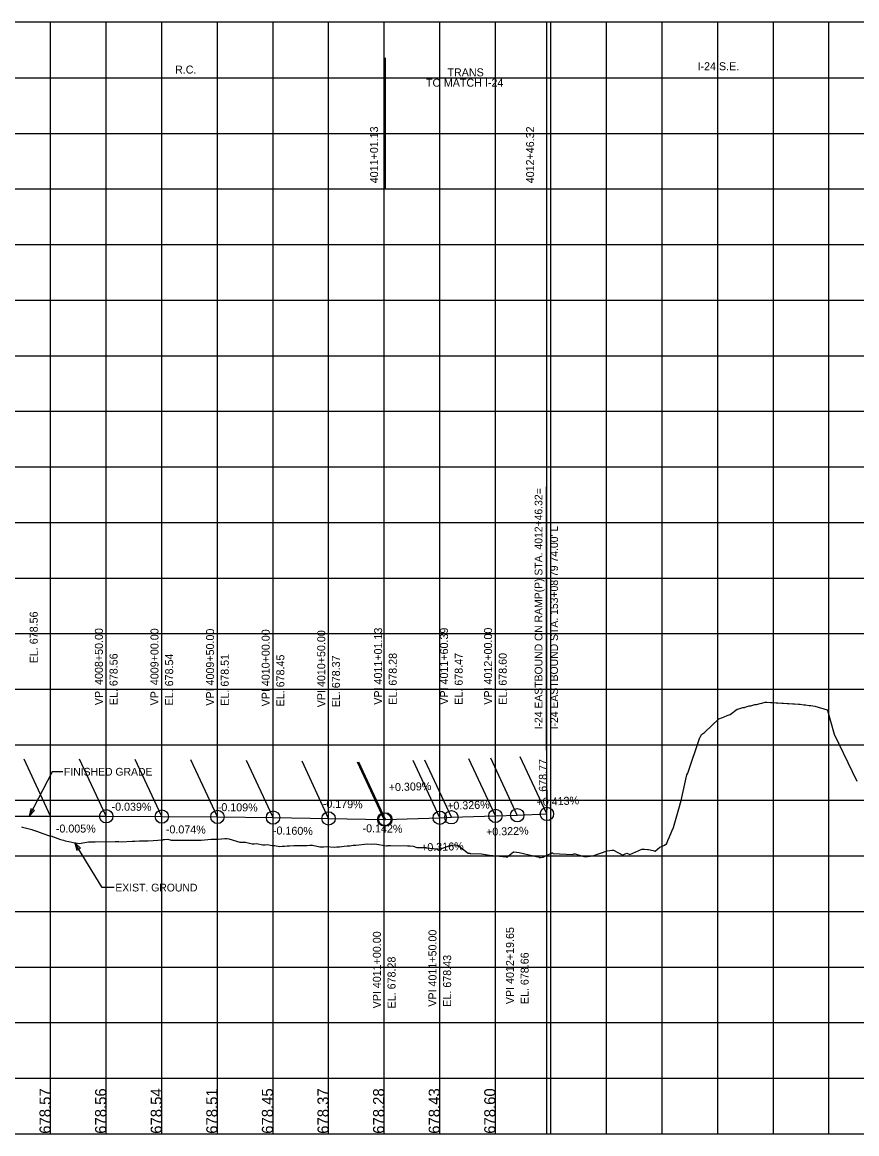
# Model space of a CAD drawing. Extents: x -7164 to 2214450, y -19642 to 253469.
# Drawn here: x 774 to 1525, y 6000 to 7000 of the extents above; entities that cross this region are included whole.
import ezdxf

# ---------------------------------------------------------------- set-up
doc = ezdxf.new("R2010")
doc.units = 0
for name, color, linetype in [('DESIGN - PROFILE - Proposed', 7, 'Continuous'), ('DESIGN - PROFILE - Proposed Curve Text', 7, 'Continuous'), ('DESIGN - PROFILE - Proposed Text', 7, 'Continuous'), ('DESIGN - SCRATCH - User 1', 7, 'Continuous'), ('DESIGN - SHEET - Light Grid', 7, 'Continuous'), ('SURVEY - PROFILE - Ground Line with Text', 7, 'Continuous')]:
    doc.layers.add(name, color=color, linetype=linetype)

msp = doc.modelspace()

# ---------------------------------------------------------------- linework, layer by layer
at = {"layer": 'DESIGN - PROFILE - Proposed'}
for p, q in [((766.8, 6285.6), (800, 6285.7)), ((766.8, 6285.6), (800, 6285.7)), ((800, 6285.7), (850, 6285.6)), ((800, 6285.7), (850, 6285.6)), ((850, 6285.6), (900, 6285.4)), ((850, 6285.6), (900, 6285.4)), ((900, 6285.4), (950, 6285.1)), ((900, 6285.4), (950, 6285.1)), ((950, 6285.1), (1000, 6284.5)), ((950, 6285.1), (1000, 6284.5)), ((1000, 6284.5), (1050, 6283.7)), ((1000, 6284.5), (1050, 6283.7)), ((1050, 6283.7), (1100, 6282.8)), ((1050, 6283.7), (1100, 6282.8)), ((1100, 6282.8), (1101.1, 6282.8)), ((1100, 6282.8), (1101.1, 6282.8)), ((1101.1, 6282.8), (1150, 6284.3)), ((1101.1, 6282.8), (1150, 6284.3)), ((1150, 6284.3), (1160.4, 6284.7)), ((1150, 6284.3), (1160.4, 6284.7)), ((1160.4, 6284.7), (1200, 6286)), ((1160.4, 6284.7), (1200, 6286)), ((1200, 6286), (1219.7, 6286.6)), ((1200, 6286), (1219.7, 6286.6)), ((1219.7, 6286.6), (1246.3, 6287.7)), ((1219.7, 6286.6), (1246.3, 6287.7))]:
    msp.add_line(p, q, dxfattribs=at)
at = {"layer": 'DESIGN - PROFILE - Proposed Curve Text'}
for p, q in [((1101.1, 6850), (1101.1, 6968.1)), ((1101.1, 6850), (1101.1, 6968.1)), ((1246.3, 6850), (1246.3, 6968.1)), ((1246.3, 6850), (1246.3, 6968.1)), ((741.8, 6950), (1101.1, 6950)), ((741.8, 6950), (1101.1, 6950)), ((1101.1, 6950), (1246.3, 6950)), ((1101.1, 6950), (1246.3, 6950)), ((1246.3, 6950), (2600, 6950)), ((1246.3, 6950), (2600, 6950))]:
    msp.add_line(p, q, dxfattribs=at)
at = {"layer": 'DESIGN - PROFILE - Proposed Text'}
msp.add_line((1245.8, 6582), (1245.8, 6362.8), dxfattribs=at)
msp.add_line((1245.8, 6582), (1245.8, 6362.8), dxfattribs=at)
for points in [[(1245.8, 6362.8), (1246.3, 6291.4)], [(1245.8, 6362.8), (1246.3, 6291.4)], [(811, 6325.7), (801.5, 6325.7), (780.6, 6285.6)], [(811, 6325.7), (801.5, 6325.7), (780.6, 6285.6)], [(857.2, 6221.5), (846.5, 6221.5), (821.7, 6261.7)], [(857.2, 6221.5), (846.5, 6221.5), (821.7, 6261.7)]]:
    msp.add_lwpolyline(points, dxfattribs=at)
for points in [[(782.1, 6292.4), (780.6, 6285.6), (785.4, 6290.8)], [(782.1, 6292.4), (780.6, 6285.6), (785.4, 6290.8)], [(826.8, 6256.9), (821.7, 6261.7), (823.7, 6255)], [(826.8, 6256.9), (821.7, 6261.7), (823.7, 6255)]]:
    msp.add_lwpolyline(points, close=True, dxfattribs=at)
for centre in [(850, 6285.6), (850, 6285.6), (900, 6285.4), (900, 6285.4), (950, 6285.1), (950, 6285.1), (1000, 6284.5), (1000, 6284.5), (1150, 6284.3), (1150, 6284.3), (1160.4, 6284.7), (1160.4, 6284.7), (1200, 6286), (1200, 6286), (1219.7, 6286.6), (1219.7, 6286.6), (1246.3, 6287.7), (1246.3, 6287.7), (1050, 6283.7), (1050, 6283.7), (1100, 6282.8), (1100, 6282.8), (1101.1, 6282.8), (1101.1, 6282.8)]:
    msp.add_circle(centre, 6, dxfattribs=at)
at = {"layer": 'DESIGN - SCRATCH - User 1'}
for p, q in [((2700, 7000), (0, 7000)), ((2700, 7000), (0, 7000)), ((800, 6285.7), (776.1, 6337)), ((800, 6285.7), (776.1, 6337)), ((850, 6285.6), (826.1, 6337)), ((850, 6285.6), (826.1, 6337)), ((900, 6285.4), (876.1, 6336.8)), ((900, 6285.4), (876.1, 6336.8)), ((950, 6285.1), (926.1, 6336.5)), ((950, 6285.1), (926.1, 6336.5)), ((1000, 6284.5), (976.1, 6335.9)), ((1000, 6284.5), (976.1, 6335.9)), ((1050, 6283.7), (1026.1, 6335.1)), ((1050, 6283.7), (1026.1, 6335.1)), ((1100, 6282.8), (1076.1, 6334.2)), ((1100, 6282.8), (1076.1, 6334.2)), ((1101.1, 6282.8), (1077.3, 6334.2)), ((1101.1, 6282.8), (1077.3, 6334.2)), ((1150, 6284.3), (1126.1, 6335.7)), ((1150, 6284.3), (1126.1, 6335.7)), ((1160.4, 6284.7), (1136.5, 6336)), ((1160.4, 6284.7), (1136.5, 6336)), ((1200, 6286), (1176.1, 6337.3)), ((1200, 6286), (1176.1, 6337.3)), ((1219.7, 6286.6), (1195.8, 6338)), ((1219.7, 6286.6), (1195.8, 6338)), ((1246.3, 6287.7), (1222.4, 6339.1)), ((1246.3, 6287.7), (1222.4, 6339.1)), ((0, 6000), (2700, 6000)), ((0, 6000), (2700, 6000))]:
    msp.add_line(p, q, dxfattribs=at)
msp.add_lwpolyline([(0, 6000), (1246.3, 6000), (1246.3, 7000)], dxfattribs=at)
msp.add_lwpolyline([(0, 6000), (1246.3, 6000), (1246.3, 7000)], dxfattribs=at)
at = {"layer": 'DESIGN - SHEET - Light Grid'}
for p, q in [((800, 6000), (800, 7000)), ((800, 6000), (800, 7000)), ((850, 6000), (850, 7000)), ((850, 6000), (850, 7000)), ((900, 6000), (900, 7000)), ((900, 6000), (900, 7000)), ((950, 6000), (950, 7000)), ((950, 6000), (950, 7000)), ((1000, 6000), (1000, 7000)), ((1000, 6000), (1000, 7000)), ((1050, 6000), (1050, 7000)), ((1050, 6000), (1050, 7000)), ((1100, 6000), (1100, 7000)), ((1100, 6000), (1100, 7000)), ((1150, 6000), (1150, 7000)), ((1150, 6000), (1150, 7000)), ((1200, 6000), (1200, 7000)), ((1200, 6000), (1200, 7000)), ((1250, 6000), (1250, 7000)), ((1250, 6000), (1250, 7000)), ((1300, 6000), (1300, 7000)), ((1300, 6000), (1300, 7000)), ((1350, 6000), (1350, 7000)), ((1350, 6000), (1350, 7000)), ((1400, 6000), (1400, 7000)), ((1400, 6000), (1400, 7000)), ((1450, 6000), (1450, 7000)), ((1450, 6000), (1450, 7000)), ((1500, 6000), (1500, 7000)), ((1500, 6000), (1500, 7000)), ((0, 6950), (2700, 6950)), ((0, 6950), (2700, 6950)), ((0, 6900), (2700, 6900)), ((0, 6900), (2700, 6900)), ((0, 6850), (2700, 6850)), ((0, 6850), (2700, 6850)), ((0, 6800), (2700, 6800)), ((0, 6800), (2700, 6800)), ((0, 6750), (2700, 6750)), ((0, 6750), (2700, 6750)), ((0, 6700), (2700, 6700)), ((0, 6700), (2700, 6700)), ((0, 6650), (2700, 6650)), ((0, 6650), (2700, 6650)), ((0, 6600), (2700, 6600)), ((0, 6600), (2700, 6600)), ((0, 6550), (2700, 6550)), ((0, 6550), (2700, 6550)), ((0, 6500), (2700, 6500)), ((0, 6500), (2700, 6500)), ((0, 6450), (2700, 6450)), ((0, 6450), (2700, 6450)), ((0, 6400), (2700, 6400)), ((0, 6400), (2700, 6400)), ((0, 6350), (2700, 6350)), ((0, 6350), (2700, 6350)), ((0, 6300), (2700, 6300)), ((0, 6300), (2700, 6300)), ((0, 6250), (2700, 6250)), ((0, 6250), (2700, 6250)), ((0, 6200), (2700, 6200)), ((0, 6200), (2700, 6200)), ((0, 6150), (2700, 6150)), ((0, 6150), (2700, 6150)), ((0, 6100), (2700, 6100)), ((0, 6100), (2700, 6100)), ((0, 6050), (2700, 6050)), ((0, 6050), (2700, 6050)), ((0, 6000), (1500, 6000)), ((0, 6000), (1500, 6000))]:
    msp.add_line(p, q, dxfattribs=at)
at = {"layer": 'SURVEY - PROFILE - Ground Line with Text'}
for points in [[(1316.6, 6251.7), (1318.3, 6252.5), (1321, 6251.3), (1331.8, 6256), (1334.1, 6255.9), (1336.8, 6255.8), (1337.8, 6255.6), (1342, 6254.7), (1343.7, 6254.3), (1347.8, 6257.7), (1352.2, 6259.7), (1353.4, 6260.4), (1353.8, 6260.4), (1355.1, 6263.7), (1356.5, 6267), (1358.8, 6272.3), (1360.3, 6275.6), (1365, 6292.2), (1367.1, 6299.9), (1372.1, 6322.9), (1373.1, 6324.4), (1384, 6356.4), (1384.4, 6357.2), (1384.8, 6357.9), (1385.2, 6358.5), (1385.4, 6359.2), (1385.4, 6359.3), (1388, 6361.1), (1401.1, 6373.3), (1404.3, 6374.5), (1405.9, 6375.2), (1408.5, 6376.2), (1411, 6377.2), (1417.4, 6382.1), (1419, 6382.2), (1422.4, 6383.5), (1424, 6383.5), (1424.7, 6383.8), (1428.2, 6384.9), (1429.7, 6385), (1433.2, 6386.1), (1434.7, 6386.2), (1438.2, 6387.2), (1439.7, 6387.3), (1442.5, 6388.2), (1444, 6388.2), (1447.5, 6388), (1449, 6388), (1452.5, 6387.8), (1452.5, 6387.8), (1454, 6387.7), (1457.5, 6387.5), (1459, 6387.4), (1462.5, 6387.2), (1464, 6387.1), (1467.5, 6386.8), (1469, 6386.8), (1472.5, 6386.5), (1472.5, 6386.5), (1474.1, 6386.4), (1477.5, 6385.8), (1478.8, 6385.9), (1482.3, 6385.2), (1483.8, 6385.4), (1487.3, 6384.7), (1498.3, 6381.5), (1498.4, 6381.5), (1498.6, 6380.8), (1504.6, 6359.4), (1525.1, 6317.1)], [(1316.6, 6251.7), (1318.3, 6252.5), (1321, 6251.3), (1331.8, 6256), (1334.1, 6255.9), (1336.8, 6255.8), (1337.8, 6255.6), (1342, 6254.7), (1343.7, 6254.3), (1347.8, 6257.7), (1352.2, 6259.7), (1353.4, 6260.4), (1353.8, 6260.4), (1355.1, 6263.7), (1356.5, 6267), (1358.8, 6272.3), (1360.3, 6275.6), (1365, 6292.2), (1367.1, 6299.9), (1372.1, 6322.9), (1373.1, 6324.4), (1384, 6356.4), (1384.4, 6357.2), (1384.8, 6357.9), (1385.2, 6358.5), (1385.4, 6359.2), (1385.4, 6359.3), (1388, 6361.1), (1401.1, 6373.3), (1404.3, 6374.5), (1405.9, 6375.2), (1408.5, 6376.2), (1411, 6377.2), (1417.4, 6382.1), (1419, 6382.2), (1422.4, 6383.5), (1424, 6383.5), (1424.7, 6383.8), (1428.2, 6384.9), (1429.7, 6385), (1433.2, 6386.1), (1434.7, 6386.2), (1438.2, 6387.2), (1439.7, 6387.3), (1442.5, 6388.2), (1444, 6388.2), (1447.5, 6388), (1449, 6388), (1452.5, 6387.8), (1452.5, 6387.8), (1454, 6387.7), (1457.5, 6387.5), (1459, 6387.4), (1462.5, 6387.2), (1464, 6387.1), (1467.5, 6386.8), (1469, 6386.8), (1472.5, 6386.5), (1472.5, 6386.5), (1474.1, 6386.4), (1477.5, 6385.8), (1478.8, 6385.9), (1482.3, 6385.2), (1483.8, 6385.4), (1487.3, 6384.7), (1498.3, 6381.5), (1498.4, 6381.5), (1498.6, 6380.8), (1504.6, 6359.4), (1525.1, 6317.1)], [(773.9, 6276), (774.8, 6275.7), (783, 6273.7), (783.8, 6273.4), (786.3, 6272.5), (786.6, 6272.4), (787.3, 6272.2), (791.4, 6270.7), (792, 6270.5), (798.9, 6268), (801, 6267.7), (801.8, 6267.4), (808.9, 6264.7), (811.6, 6264.1), (813.1, 6263.4), (816.3, 6262.8), (821.7, 6261.7), (822.6, 6261.6), (825.6, 6261), (830.8, 6261.9), (834.1, 6262.5), (836.6, 6262.5), (838.7, 6262.5), (838.8, 6262.5), (840.2, 6262.6), (858.1, 6262.8), (858.1, 6262.8), (861.2, 6263), (863.4, 6262.6), (873.2, 6263.2), (875.5, 6263.1), (875.6, 6263.1), (879.9, 6263.4), (881.2, 6263.4), (883.7, 6263.6), (887.6, 6263.4), (900.9, 6264.5), (901.5, 6264.6), (902.3, 6264.6), (905.5, 6264.9), (908.5, 6264.1), (909.9, 6264.2), (916.5, 6264), (917.9, 6264.1), (918.1, 6264.1), (920.2, 6264), (921.7, 6264.1), (922.4, 6264.1), (923.9, 6264.1), (932.2, 6264), (933.8, 6264), (935.4, 6264.1), (944.4, 6264.9), (946.1, 6264.9), (947.8, 6265), (948.9, 6265.1), (950.6, 6265.1), (956.7, 6265.6), (958.4, 6265.5), (960.2, 6265.3), (970.1, 6262.3), (971.6, 6262.2)], [(773.9, 6276), (774.8, 6275.7), (783, 6273.7), (783.8, 6273.4), (786.3, 6272.5), (786.6, 6272.4), (787.3, 6272.2), (791.4, 6270.7), (792, 6270.5), (798.9, 6268), (801, 6267.7), (801.8, 6267.4), (808.9, 6264.7), (811.6, 6264.1), (813.1, 6263.4), (816.3, 6262.8), (821.7, 6261.7), (822.6, 6261.6), (825.6, 6261), (830.8, 6261.9), (834.1, 6262.5), (836.6, 6262.5), (838.7, 6262.5), (838.8, 6262.5), (840.2, 6262.6), (858.1, 6262.8), (858.1, 6262.8), (861.2, 6263), (863.4, 6262.6), (873.2, 6263.2), (875.5, 6263.1), (875.6, 6263.1), (879.9, 6263.4), (881.2, 6263.4), (883.7, 6263.6), (887.6, 6263.4), (900.9, 6264.5), (901.5, 6264.6), (902.3, 6264.6), (905.5, 6264.9), (908.5, 6264.1), (909.9, 6264.2), (916.5, 6264), (917.9, 6264.1), (918.1, 6264.1), (920.2, 6264), (921.7, 6264.1), (922.4, 6264.1), (923.9, 6264.1), (932.2, 6264), (933.8, 6264), (935.4, 6264.1), (944.4, 6264.9), (946.1, 6264.9), (947.8, 6265), (948.9, 6265.1), (950.6, 6265.1), (956.7, 6265.6), (958.4, 6265.5), (960.2, 6265.3), (970.1, 6262.3), (971.6, 6262.2)], [(971.6, 6262.2), (973.5, 6262.3), (975.4, 6262.4), (981.2, 6260.7), (983.2, 6260.8), (985.2, 6261), (990.8, 6259.8), (992.9, 6260), (995, 6260.1), (997.8, 6259.5), (999.2, 6259.3), (1001.4, 6259.4), (1006, 6258.5), (1008.2, 6258.6), (1010.4, 6258.8), (1012.6, 6258.9), (1014.9, 6259.1), (1018.6, 6259.2), (1020.9, 6259.2), (1026.2, 6259.4), (1028.5, 6259.4), (1030.8, 6259.4), (1033.2, 6259.5), (1035.6, 6259.5), (1042, 6258.1), (1043.5, 6258.1), (1045.8, 6258.2), (1048.2, 6258.3), (1054.9, 6257.9), (1057.3, 6258), (1059.8, 6258.1), (1064, 6258.8), (1066.6, 6258.9), (1069.1, 6259), (1072, 6259.5), (1074.6, 6259.6), (1077.3, 6259.8), (1082.3, 6260.6), (1085, 6260.7), (1088.9, 6260.6), (1091.6, 6260.7), (1102, 6259.1), (1102.7, 6259.1), (1103.5, 6259.2), (1104.3, 6259.2), (1105, 6259.2), (1105.7, 6259.2), (1120.9, 6259), (1123.5, 6258.9), (1126, 6258.8), (1129.4, 6257.6), (1131.7, 6257.6), (1134, 6257.4), (1144.2, 6256.5), (1145.7, 6256.4), (1147.2, 6256.3), (1148.6, 6256.2), (1150, 6256.1), (1159.9, 6259.7), (1163.4, 6259.8), (1164.2, 6259.9), (1166.4, 6259.3), (1175.5, 6252.5), (1177.4, 6252.3), (1177.4, 6252.2), (1187.5, 6251.8), (1189.4, 6251.5), (1191.2, 6251.3), (1193, 6251), (1194.7, 6250.7), (1209.7, 6249), (1210.4, 6248.8), (1216.2, 6253.5), (1216.7, 6253.5), (1221.3, 6252.9), (1239.3, 6248.7), (1239.5, 6248.6), (1240.1, 6248.6), (1240.7, 6248.6), (1242.3, 6248.9), (1242.9, 6248.9), (1246.3, 6250.6), (1247.7, 6251.3), (1250.7, 6252.5), (1251, 6252.6), (1251.8, 6252.7), (1252, 6252.2), (1269.4, 6251.3), (1270.6, 6251.9), (1271.6, 6251.9), (1273.4, 6251.3), (1279.5, 6249.3), (1282.8, 6249.5), (1287.5, 6250.1), (1300.4, 6254.6), (1303, 6254.9), (1304.8, 6255), (1306.2, 6255.2), (1314.6, 6250.7), (1314.8, 6250.8), (1316.6, 6251.7)], [(971.6, 6262.2), (973.5, 6262.3), (975.4, 6262.4), (981.2, 6260.7), (983.2, 6260.8), (985.2, 6261), (990.8, 6259.8), (992.9, 6260), (995, 6260.1), (997.8, 6259.5), (999.2, 6259.3), (1001.4, 6259.4), (1006, 6258.5), (1008.2, 6258.6), (1010.4, 6258.8), (1012.6, 6258.9), (1014.9, 6259.1), (1018.6, 6259.2), (1020.9, 6259.2), (1026.2, 6259.4), (1028.5, 6259.4), (1030.8, 6259.4), (1033.2, 6259.5), (1035.6, 6259.5), (1042, 6258.1), (1043.5, 6258.1), (1045.8, 6258.2), (1048.2, 6258.3), (1054.9, 6257.9), (1057.3, 6258), (1059.8, 6258.1), (1064, 6258.8), (1066.6, 6258.9), (1069.1, 6259), (1072, 6259.5), (1074.6, 6259.6), (1077.3, 6259.8), (1082.3, 6260.6), (1085, 6260.7), (1088.9, 6260.6), (1091.6, 6260.7), (1102, 6259.1), (1102.7, 6259.1), (1103.5, 6259.2), (1104.3, 6259.2), (1105, 6259.2), (1105.7, 6259.2), (1120.9, 6259), (1123.5, 6258.9), (1126, 6258.8), (1129.4, 6257.6), (1131.7, 6257.6), (1134, 6257.4), (1144.2, 6256.5), (1145.7, 6256.4), (1147.2, 6256.3), (1148.6, 6256.2), (1150, 6256.1), (1159.9, 6259.7), (1163.4, 6259.8), (1164.2, 6259.9), (1166.4, 6259.3), (1175.5, 6252.5), (1177.4, 6252.3), (1177.4, 6252.2), (1187.5, 6251.8), (1189.4, 6251.5), (1191.2, 6251.3), (1193, 6251), (1194.7, 6250.7), (1209.7, 6249), (1210.4, 6248.8), (1216.2, 6253.5), (1216.7, 6253.5), (1221.3, 6252.9), (1239.3, 6248.7), (1239.5, 6248.6), (1240.1, 6248.6), (1240.7, 6248.6), (1242.3, 6248.9), (1242.9, 6248.9), (1246.3, 6250.6), (1247.7, 6251.3), (1250.7, 6252.5), (1251, 6252.6), (1251.8, 6252.7), (1252, 6252.2), (1269.4, 6251.3), (1270.6, 6251.9), (1271.6, 6251.9), (1273.4, 6251.3), (1279.5, 6249.3), (1282.8, 6249.5), (1287.5, 6250.1), (1300.4, 6254.6), (1303, 6254.9), (1304.8, 6255), (1306.2, 6255.2), (1314.6, 6250.7), (1314.8, 6250.8), (1316.6, 6251.7)]]:
    msp.add_lwpolyline(points, dxfattribs=at)

# ---------------------------------------------------------------- texts
at = {"layer": 'DESIGN - PROFILE - Proposed Curve Text'}
for s, p in [('R.C.', (911.9, 6953.8)), ('I-24 S.E.', (1381.8, 6956.8)), ('TRANS', (1156.9, 6951.3)), ('TO MATCH I-24', (1137.6, 6942))]:
    msp.add_text(s, height=7.2, dxfattribs=at).set_placement(p)
for s, rotation, p in [('R.C.', 360, (911.9, 6953.8)), ('I-24 S.E.', 360, (1381.8, 6956.8)), ('TRANS', 360, (1156.9, 6951.3)), ('TO MATCH I-24', 360, (1137.6, 6942)), ('4011+01.13', 90, (1094.5, 6855.1)), ('4011+01.13', 90, (1094.5, 6855.1)), ('4012+46.32', 90, (1234.8, 6855.1)), ('4012+46.32', 90, (1234.8, 6855.1)), ('VPI 4008+50.00', 90, (847, 6385.6)), ('VPI 4008+50.00', 90, (847, 6385.6)), ('VPI 4009+00.00', 90, (897, 6385.4)), ('VPI 4009+00.00', 90, (897, 6385.4)), ('VPI 4009+50.00', 90, (947, 6385.1)), ('VPI 4009+50.00', 90, (947, 6385.1)), ('VPI 4010+00.00', 90, (997, 6384.5)), ('VPI 4010+00.00', 90, (997, 6384.5)), ('VPI 4010+50.00', 90, (1047, 6383.7)), ('VPI 4010+50.00', 90, (1047, 6383.7)), ('VPI 4011+01.13', 90, (1098.1, 6386)), ('VPI 4011+01.13', 90, (1098.1, 6386)), ('VPI 4011+60.39', 90, (1157.4, 6386)), ('VPI 4011+60.39', 90, (1157.4, 6386)), ('VPI 4012+00.00', 90, (1197, 6386)), ('VPI 4012+00.00', 90, (1197, 6386)), ('EL. 678.56', 90, (860.2, 6385.6)), ('EL. 678.56', 90, (860.2, 6385.6)), ('EL. 678.54', 90, (910.2, 6385.4)), ('EL. 678.54', 90, (910.2, 6385.4)), ('EL. 678.51', 90, (960.2, 6385.1)), ('EL. 678.51', 90, (960.2, 6385.1)), ('EL. 678.45', 90, (1010.2, 6384.5)), ('EL. 678.45', 90, (1010.2, 6384.5)), ('EL. 678.28', 90, (1111.3, 6386)), ('EL. 678.28', 90, (1111.3, 6386)), ('EL. 678.47', 90, (1170.6, 6386)), ('EL. 678.47', 90, (1170.6, 6386)), ('EL. 678.60', 90, (1210.2, 6386)), ('EL. 678.60', 90, (1210.2, 6386)), ('EL. 678.37', 90, (1060.2, 6383.7)), ('EL. 678.37', 90, (1060.2, 6383.7)), ('678.77', 90, (1246.3, 6307.7)), ('678.77', 90, (1246.3, 6307.7)), ('VPI 4011+00.00', 90, (1097, 6112.8)), ('VPI 4011+00.00', 90, (1097, 6112.8)), ('VPI 4011+50.00', 90, (1147, 6114.3)), ('VPI 4011+50.00', 90, (1147, 6114.3)), ('VPI 4012+19.65', 90, (1216.7, 6116.6)), ('VPI 4012+19.65', 90, (1216.7, 6116.6)), ('EL. 678.43', 90, (1160.2, 6114.3)), ('EL. 678.43', 90, (1160.2, 6114.3)), ('EL. 678.66', 90, (1229.9, 6116.6)), ('EL. 678.66', 90, (1229.9, 6116.6)), ('EL. 678.28', 90, (1110.2, 6112.8)), ('EL. 678.28', 90, (1110.2, 6112.8))]:
    msp.add_text(s, height=7.2, rotation=rotation, dxfattribs=at).set_placement(p)
at = {"layer": 'DESIGN - PROFILE - Proposed Text'}
for s, height, rotation, p in [('I-24 EASTBOUND ON RAMP(P) STA. 4012+46.32=', 7, 90, (1242.3, 6363.8)), ('I-24 EASTBOUND ON RAMP(P) STA. 4012+46.32=', 7, 90, (1242.3, 6363.8)), ("I-24 EASTBOUND STA. 153+08.79 74.00' LT", 7, 90, (1256.3, 6363.8)), ('I-24 EASTBOUND STA. 153+08.79', 7, 90, (1256.3, 6363.8)), ('EL. 678.56', 7.2, 90, (788.4, 6423.3)), ('EL. 678.56', 7.2, 90, (788.4, 6423.3)), ('+0.309%', 7.2, 1.771, (1104.2, 6308.1)), ('+0.309%', 7.2, 1.771, (1104.2, 6308.1)), ('-0.179%', 7.2, 358.9722, (1044.7, 6293.4)), ('-0.179%', 7.2, 358.9722, (1044.7, 6293.4)), ('+0.413%', 7.2, 2.3661, (1237.1, 6294.8)), ('+0.413%', 7.2, 2.3661, (1237.1, 6294.8)), ('-0.039%', 7.2, 359.7754, (854.8, 6290.7)), ('-0.039%', 7.2, 359.7754, (854.8, 6290.7)), ('-0.109%', 7.2, 359.3778, (950.3, 6290.3)), ('-0.109%', 7.2, 359.3778, (950.3, 6290.3)), ('+0.326%', 7.2, 1.8653, (1156.7, 6291.4)), ('+0.326%', 7.2, 1.8653, (1156.7, 6291.4)), ('-0.005%', 7.2, 359.9725, (804.7, 6271)), ('-0.005%', 7.2, 359.9725, (804.7, 6271)), ('-0.074%', 7.2, 359.5772, (903.6, 6270.3)), ('-0.074%', 7.2, 359.5772, (903.6, 6270.3)), ('-0.160%', 7.2, 359.0856, (999.9, 6269.3)), ('-0.160%', 7.2, 359.0856, (999.9, 6269.3)), ('-0.142%', 7.2, 359.1888, (1080.5, 6271.3)), ('-0.142%', 7.2, 359.1888, (1080.5, 6271.3)), ('+0.322%', 7.2, 1.8422, (1191.7, 6268)), ('+0.322%', 7.2, 1.8422, (1191.7, 6268)), ('+0.316%', 7.2, 1.8082, (1133.3, 6254)), ('+0.316%', 7.2, 1.8082, (1133.3, 6254)), ('678.57', 10, 90, (800, 6000)), ('678.57', 10, 90, (800, 6000)), ('678.56', 10, 90, (850, 6000)), ('678.56', 10, 90, (850, 6000)), ('678.54', 10, 90, (900, 6000)), ('678.54', 10, 90, (900, 6000)), ('678.51', 10, 90, (950, 6000)), ('678.51', 10, 90, (950, 6000)), ('678.45', 10, 90, (1000, 6000)), ('678.45', 10, 90, (1000, 6000)), ('678.37', 10, 90, (1050, 6000)), ('678.37', 10, 90, (1050, 6000)), ('678.28', 10, 90, (1100, 6000)), ('678.28', 10, 90, (1100, 6000)), ('678.43', 10, 90, (1150, 6000)), ('678.43', 10, 90, (1150, 6000)), ('678.60', 10, 90, (1200, 6000)), ('678.60', 10, 90, (1200, 6000))]:
    msp.add_text(s, height=height, rotation=rotation, dxfattribs=at).set_placement(p)
for s, p in [('FINISHED GRADE', (812, 6322.2)), ('FINISHED GRADE', (812, 6322.2)), ('EXIST. GROUND', (858.2, 6218)), ('EXIST. GROUND', (858.2, 6218))]:
    msp.add_text(s, height=7, dxfattribs=at).set_placement(p)

doc.saveas('drawing.dxf')
